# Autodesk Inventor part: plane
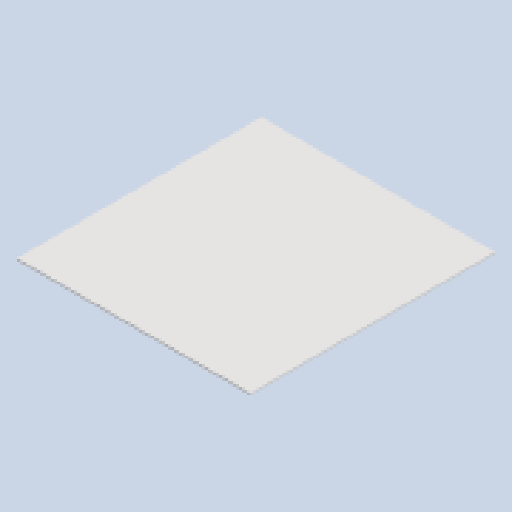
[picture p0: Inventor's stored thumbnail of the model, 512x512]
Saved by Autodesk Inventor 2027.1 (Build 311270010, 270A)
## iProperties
Created: 2026-07
Part Number: plane
Material: Generic
Document SubType Name: Modeling
Designer: dunge
Density: 1 g/cm^3
Appearance: Default
Author: dunge
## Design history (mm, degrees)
sketch "Sketch1"
  geometry: L1 (173.09, 200.13)-(-203.308, 200.13); L2 (-203.308, 200.13)-(-203.308, -194.121); L3 (-203.308, -194.121)-(173.09, -194.121); L4 (173.09, -194.121)-(173.09, 200.13); 1 further point
  constraints: 8 end point, 2 parallel, 1 horizontal, 1 perpendicular
extrude "Extrusion1" new body sketch "Sketch1" distance "d0" = 2.54; taper "d1" = 0 deg
body "Solid1"
